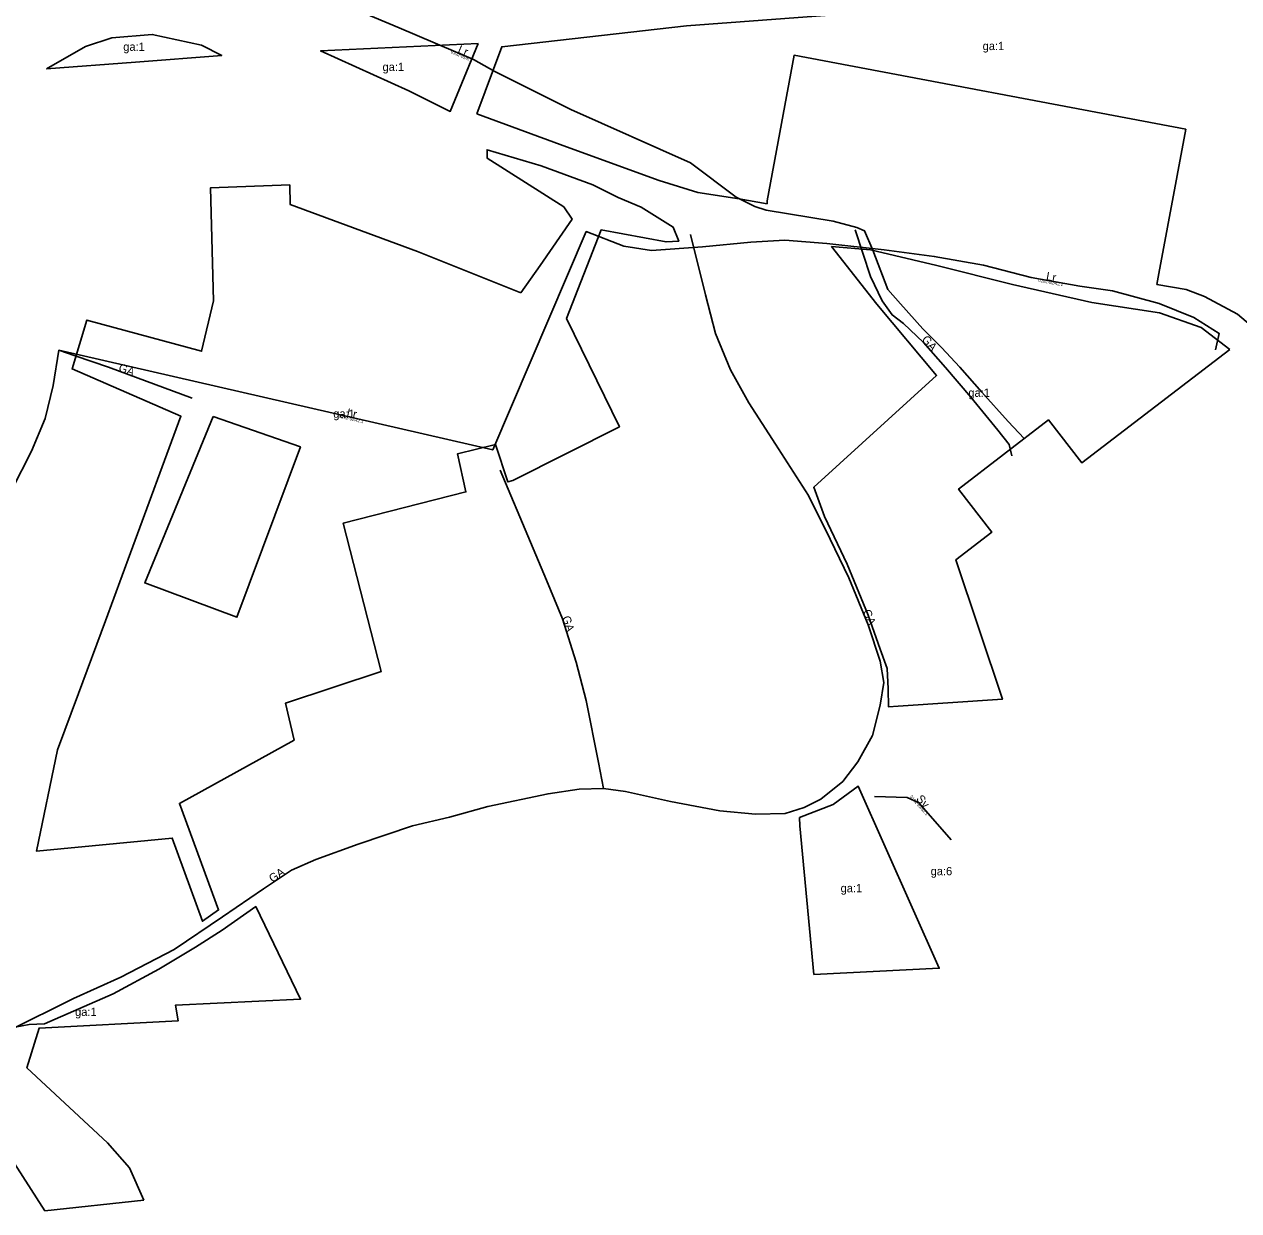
# Model space of a CAD drawing. Extents: x 140791 to 143631, y 6542790 to 6549933.
# Drawn here: x 142535 to 143048, y 6548148 to 6548650 of the extents above; entities that cross this region are included whole.
import ezdxf

# ---------------------------------------------------------------- set-up
doc = ezdxf.new("R2010")
doc.units = 0
for name, color, linetype in [('RATT Aktbeteckning för ledningsrätt', 7, 'Continuous'), ('RATT Aktbeteckning för servitut', 7, 'Continuous'), ('RATT Beteckning för gemensammhetsanläggning', 7, 'Continuous'), ('RATT Beteckning för ledningsrätt', 7, 'Continuous'), ('RATT Beteckning för servitut', 7, 'Continuous'), ('RATT Gemensamhetsanläggning', 7, 'Continuous'), ('RATT Gemensamhetsanläggningsgräns', 7, 'Continuous'), ('RATT Ledningsrätt', 7, 'Continuous'), ('RATT Servitut', 7, 'Continuous')]:
    doc.layers.add(name, color=color, linetype=linetype)

msp = doc.modelspace()

# ---------------------------------------------------------------- linework, layer by layer
at = {"layer": 'RATT Gemensamhetsanläggning'}
for points in [[(142952.41, 6548467.55), (142951.37, 6548472.27), (142946.56, 6548478.42), (142935.08, 6548492.39), (142924.3, 6548504.88), (142915.07, 6548515.41), (142906.65, 6548523.43), (142901.77, 6548527.09), (142897.54, 6548533.08), (142892.7, 6548543.34), (142886.14, 6548563.09)], [(142779.74, 6548326.82), (142788.94, 6548325.53), (142808.03, 6548321.31), (142828.89, 6548317.33), (142843.95, 6548315.87), (142856.57, 6548316.23), (142864.56, 6548318.79), (142871.56, 6548322.25), (142880.87, 6548329.76), (142887.27, 6548338.08), (142893.46, 6548349.19), (142896.76, 6548362), (142898.21, 6548371.64), (142896.71, 6548380.63), (142891.58, 6548396.03), (142883.51, 6548415.92), (142875.62, 6548432.28), (142866.47, 6548450.73), (142852.43, 6548472.4), (142841.2, 6548489.89), (142833.39, 6548503.9), (142827.09, 6548519.19), (142822.87, 6548535.59), (142816.42, 6548561.15)], [(142549.27, 6548512.14), (142556.09, 6548509.74), (142570.18, 6548504.94), (142605.59, 6548491.89)], [(142779.74, 6548326.82), (142777.56, 6548337.74), (142772.31, 6548364), (142768.08, 6548380.25), (142762.31, 6548398.61), (142755.59, 6548414.94), (142748.72, 6548430.97), (142735.96, 6548461.41)], [(142517.51, 6548219.31), (142528.21, 6548224.43), (142555.44, 6548238.01), (142575.5, 6548246.96), (142597.98, 6548258.63), (142618.47, 6548272.55), (142635.82, 6548284.37), (142647.64, 6548292.24), (142658.03, 6548296.77), (142675.82, 6548303.3), (142698.92, 6548310.99), (142714.57, 6548314.64), (142730.68, 6548319.16), (142756.21, 6548324.58), (142769.32, 6548326.54), (142779.74, 6548326.82)]]:
    msp.add_lwpolyline(points, dxfattribs=at)
at = {"layer": 'RATT Gemensamhetsanläggningsgräns'}
for points in [[(142726.08, 6548612.14), (142763.95, 6548598.2), (142803.23, 6548584.01), (142819.64, 6548578.95), (142837.04, 6548576.19), (142848.88, 6548574.12), (142848.87, 6548575.34), (142860.28, 6548636.97), (143025.98, 6548605.68), (143014.57, 6548544.64), (143013.84, 6548540.03), (143026.22, 6548537.86), (143034, 6548534.95), (143047.93, 6548527.4), (143056.24, 6548520.34), (143062.39, 6548516.19), (143070.24, 6548508.06), (143083.86, 6548556.1), (143113.56, 6548671.83), (142814.85, 6548649.35), (142736.59, 6548640.58), (142726.08, 6548612.14)], [(142544.07, 6548631.14), (142560.57, 6548640.61), (142571.68, 6548644.29), (142588.72, 6548645.8), (142609.59, 6548641.21), (142618.13, 6548636.8), (142581.67, 6548634.01), (142544.07, 6548631.14)], [(142726.63, 6548641.87), (142714.8, 6548613.21), (142697.38, 6548621.91), (142659.95, 6548638.76), (142726.63, 6548641.87)], [(142744.67, 6548536.44), (142752.84, 6548548.07), (142766.37, 6548567.59), (142762.88, 6548572.87), (142730.51, 6548593.42), (142730.41, 6548597), (142753.31, 6548590.19), (142775.17, 6548582.2), (142785.93, 6548576.79), (142795.67, 6548572.66), (142809.21, 6548564.3), (142811.5, 6548558.29), (142806.15, 6548558.02), (142778.63, 6548563.07), (142764.05, 6548525.53), (142786.42, 6548479.81), (142741.27, 6548457.12), (142739.14, 6548456.47), (142733.93, 6548472.26), (142717.96, 6548468.39), (142721.44, 6548452.23), (142669.51, 6548438.98), (142685.57, 6548376.23), (142645.15, 6548362.91), (142648.75, 6548347.26), (142600.25, 6548320.44), (142616.85, 6548275.4), (142610, 6548270.64), (142597.18, 6548305.79), (142539.85, 6548300.23), (142548.71, 6548343.09), (142557.56, 6548367.02), (142568.92, 6548397.7), (142579.59, 6548426.53), (142600.91, 6548484.22), (142554.87, 6548504.24), (142561.06, 6548524.9), (142609.63, 6548511.75), (142614.73, 6548533), (142613.46, 6548580.91), (142646.9, 6548582.14)], [(142646.9, 6548582.14), (142647.09, 6548573.86), (142700.99, 6548553.98), (142744.67, 6548536.44)], [(143044.68, 6548512.53), (143032.49, 6548521.76), (143014.91, 6548528.04), (142986.33, 6548532.41), (142952.74, 6548540.01), (142920.65, 6548548.03), (142892.62, 6548554.71), (142876.17, 6548556.04), (142895.37, 6548531.69), (142920.6, 6548501.5), (142868.61, 6548454.18), (142873.22, 6548441.86), (142882.81, 6548421.65), (142891.61, 6548400.11), (142896.68, 6548385.75), (142899.62, 6548377.51), (142900.16, 6548369), (142900.18, 6548361.36), (142904.29, 6548361.63), (142948.48, 6548364.53), (142928.79, 6548423.52), (142944, 6548435.22), (142929.93, 6548453.42), (142967.94, 6548482.71), (142982.06, 6548464.49), (143044.68, 6548512.53)], [(142614.46, 6548484.08), (142585.57, 6548413.77), (142624.55, 6548399.21), (142651.46, 6548471.28), (142614.46, 6548484.08)], [(142868.65, 6548248.16), (142921.74, 6548250.71), (142887.37, 6548327.77), (142876.8, 6548320.04), (142862.61, 6548314.47), (142862.72, 6548310.98), (142868.65, 6548248.16)], [(142585.14, 6548152.59), (142579.15, 6548166.3), (142569.8, 6548176.96), (142535.76, 6548208.56), (142540.84, 6548225.42), (142599.71, 6548228.49), (142598.66, 6548235.14), (142651.5, 6548237.73), (142632.54, 6548276.83), (142618.36, 6548266.91), (142606.99, 6548259.73), (142591.59, 6548250.39), (142572.23, 6548239.97), (142543.14, 6548227.16), (142536.68, 6548226.98), (142524.78, 6548224.73), (142507.74, 6548219.96), (142510.6, 6548207.08), (142515.53, 6548193.13), (142524.74, 6548177.16), (142543.35, 6548148.18), (142585.14, 6548152.59)]]:
    msp.add_lwpolyline(points, dxfattribs=at)
at = {"layer": 'RATT Ledningsrätt'}
for points in [[(142957.69, 6548474.88), (142950.89, 6548481.97), (142939.78, 6548494.41), (142930.47, 6548504.96), (142922.61, 6548513.36), (142914.78, 6548521.23), (142905.31, 6548531.74), (142899.94, 6548537.85), (142893.66, 6548554.5), (142890.12, 6548562.72), (142886.84, 6548564.13), (142876.81, 6548566.76), (142848.46, 6548571.38), (142843.68, 6548572.96), (142835.77, 6548576.92), (142816.41, 6548591.44), (142765.91, 6548614.03), (142733.72, 6548630.1), (142724.6, 6548635.19), (142693.25, 6548648.59), (142636.61, 6548672.42)], [(142529.38, 6548453.18), (142537.63, 6548469.51), (142543.45, 6548483.27), (142546.78, 6548497.25), (142549.27, 6548512.14), (142732.79, 6548470.02), (142772.34, 6548562.35), (142788.21, 6548556.21), (142800.02, 6548554.31), (142821.55, 6548555.87), (142841.97, 6548557.83), (142856.32, 6548558.68), (142874.18, 6548557.34), (142898.41, 6548554.66), (142919.61, 6548551.89), (142940.41, 6548548.2), (142960.59, 6548543.01), (142981.2, 6548539.32), (142995.09, 6548537.35), (143014.7, 6548532), (143029.39, 6548526.05), (143040.1, 6548519.29), (143038.55, 6548512.37)]]:
    msp.add_lwpolyline(points, dxfattribs=at)
at = {"layer": 'RATT Servitut'}
msp.add_lwpolyline([(142894.36, 6548323.46), (142908.18, 6548323.04), (142913.07, 6548320.75), (142926.79, 6548305.06)], dxfattribs=at)

# ---------------------------------------------------------------- texts
at = {"layer": 'RATT Aktbeteckning för ledningsrätt'}
for s, rotation, p in [('0192-05/8.1', 336.691, (142714.92, 6548637.93)), ('0192-92/42.1', 349.869, (142963.59, 6548541.15)), ('0192-92/42.1', 347.004, (142667.62, 6548483.65))]:
    msp.add_text(s, height=1.3, rotation=rotation, dxfattribs=at).set_placement(p)
at = {"layer": 'RATT Aktbeteckning för servitut'}
msp.add_text('0192-93/52.1', height=1.3, rotation=311.116, dxfattribs=at).set_placement((142909.22, 6548323.2))
at = {"layer": 'RATT Beteckning för gemensammhetsanläggning'}
for s, p in [('ga:1', (142576.49, 6548638.82)), ('ga:1', (142940.08, 6548639.14)), ('ga:1', (142686.19, 6548630.29)), ('ga:1', (142934.04, 6548492.46)), ('ga:1', (142665.36, 6548483.6)), ('ga:6', (142918.09, 6548290.07)), ('ga:1', (142879.99, 6548282.89)), ('ga:1', (142556.11, 6548230.55))]:
    msp.add_text(s, height=3.5, dxfattribs=at).set_placement(p)
for rotation, p in [(311.116, (142914.06, 6548516.57)), (339.764, (142574.19, 6548503.46)), (287.625, (142762.11, 6548399.19)), (292.208, (142889.27, 6548401.7)), (33.805, (142639.57, 6548286.85))]:
    msp.add_text('GA', height=3.5, rotation=rotation, dxfattribs=at).set_placement(p)
at = {"layer": 'RATT Beteckning för ledningsrätt'}
for rotation, p in [(336.691, (142717.7, 6548638.15)), (349.869, (142966.75, 6548541.91)), (347.004, (142670.81, 6548484.24))]:
    msp.add_text('Lr', height=3.5, rotation=rotation, dxfattribs=at).set_placement(p)
at = {"layer": 'RATT Beteckning för servitut'}
msp.add_text('Sv', height=3.5, rotation=311.116, dxfattribs=at).set_placement((142911.75, 6548322.27))

doc.saveas('drawing.dxf')
